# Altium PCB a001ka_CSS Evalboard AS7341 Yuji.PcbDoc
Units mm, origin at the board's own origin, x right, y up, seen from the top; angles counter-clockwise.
Board outline 40 x 29 mm, 4 copper layers (Top Layer, Signal Layer 1, Internal Plane 1, Bottom Layer), stack 1.536 mm thick; 40 components, 22 nets, 130 pads, 47 vias.
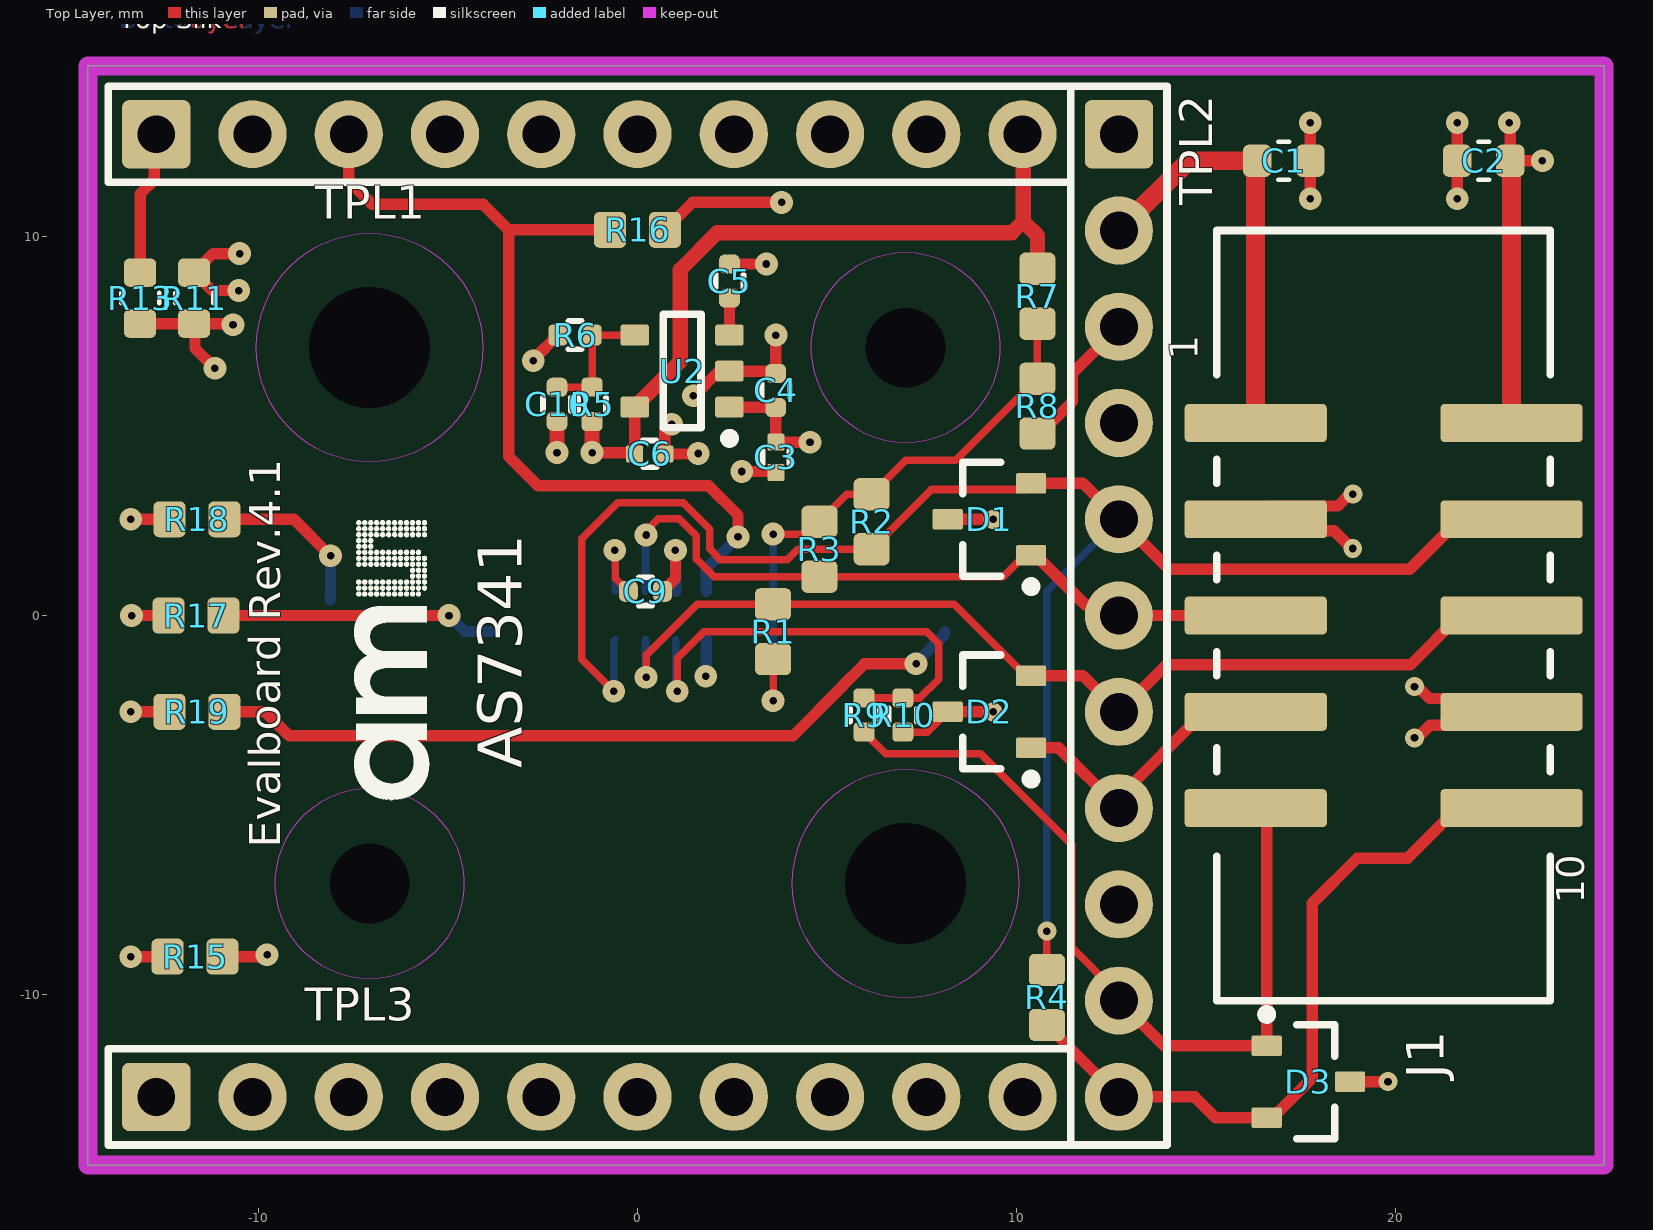
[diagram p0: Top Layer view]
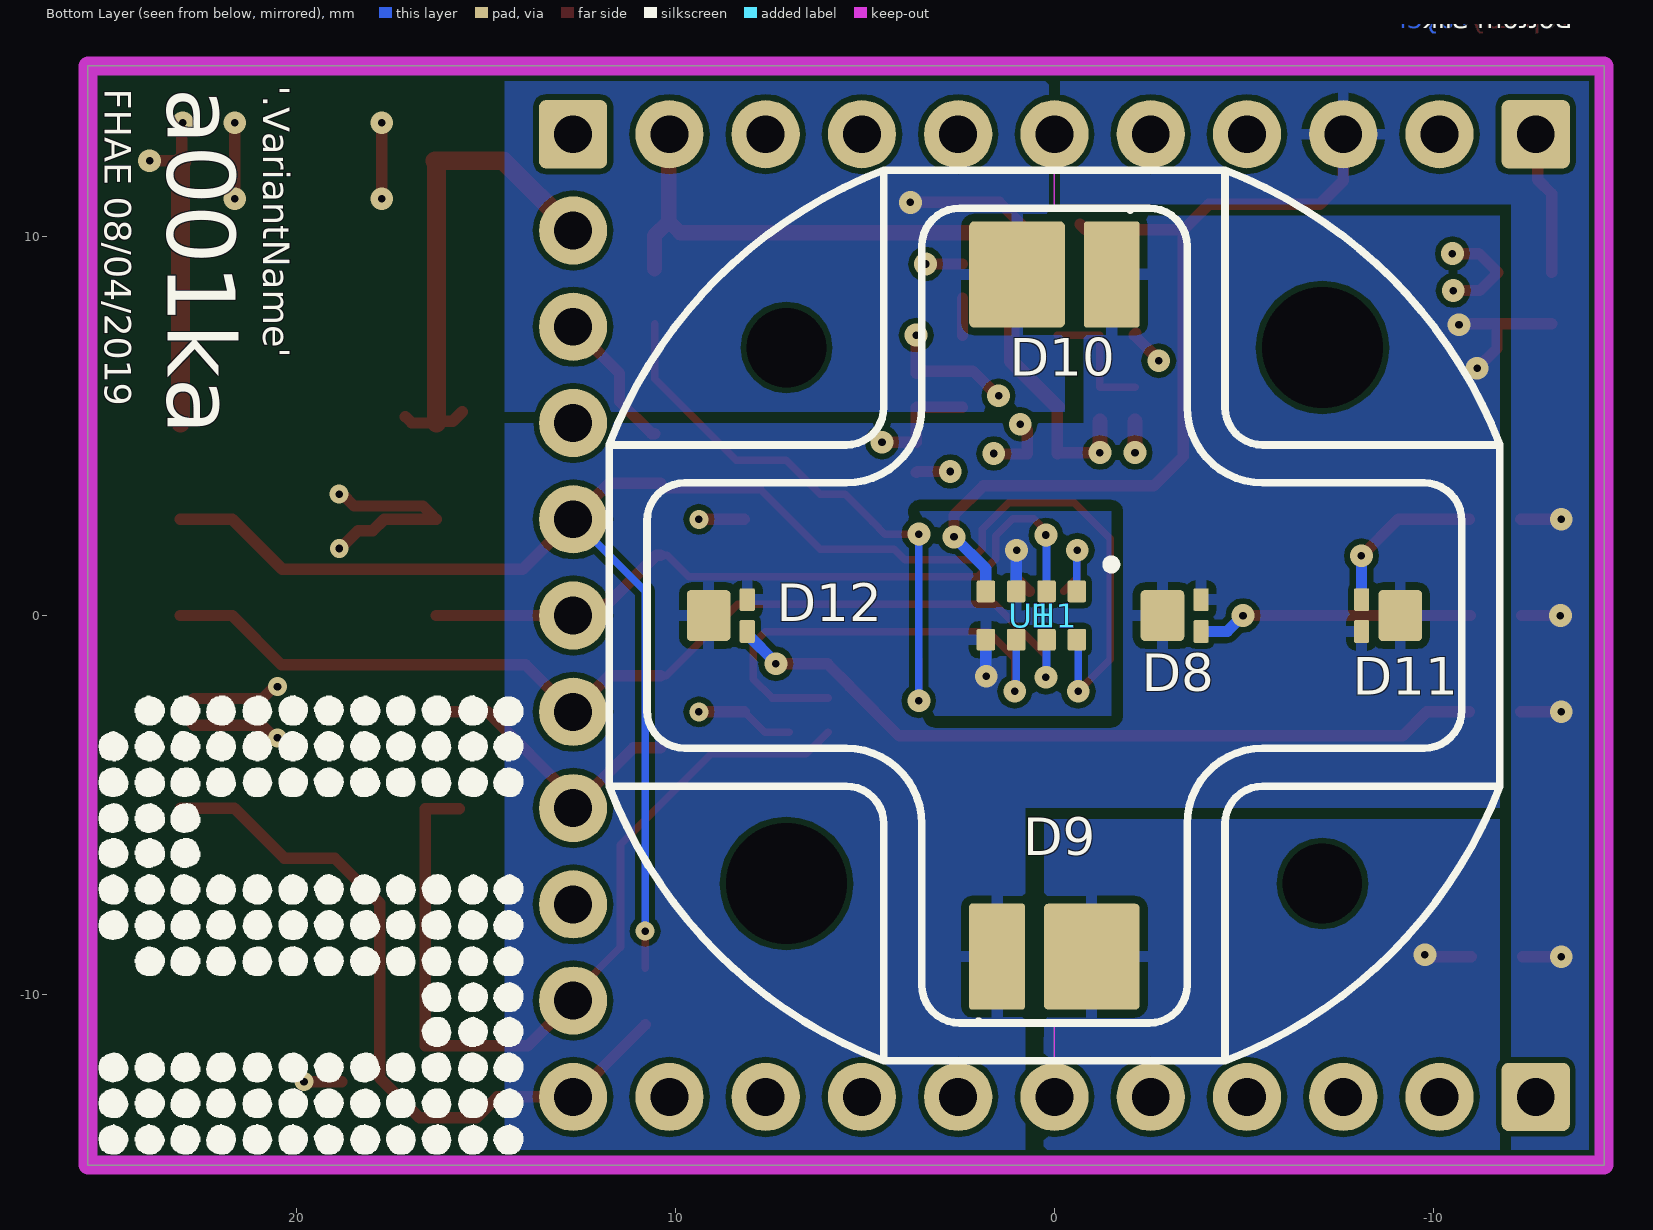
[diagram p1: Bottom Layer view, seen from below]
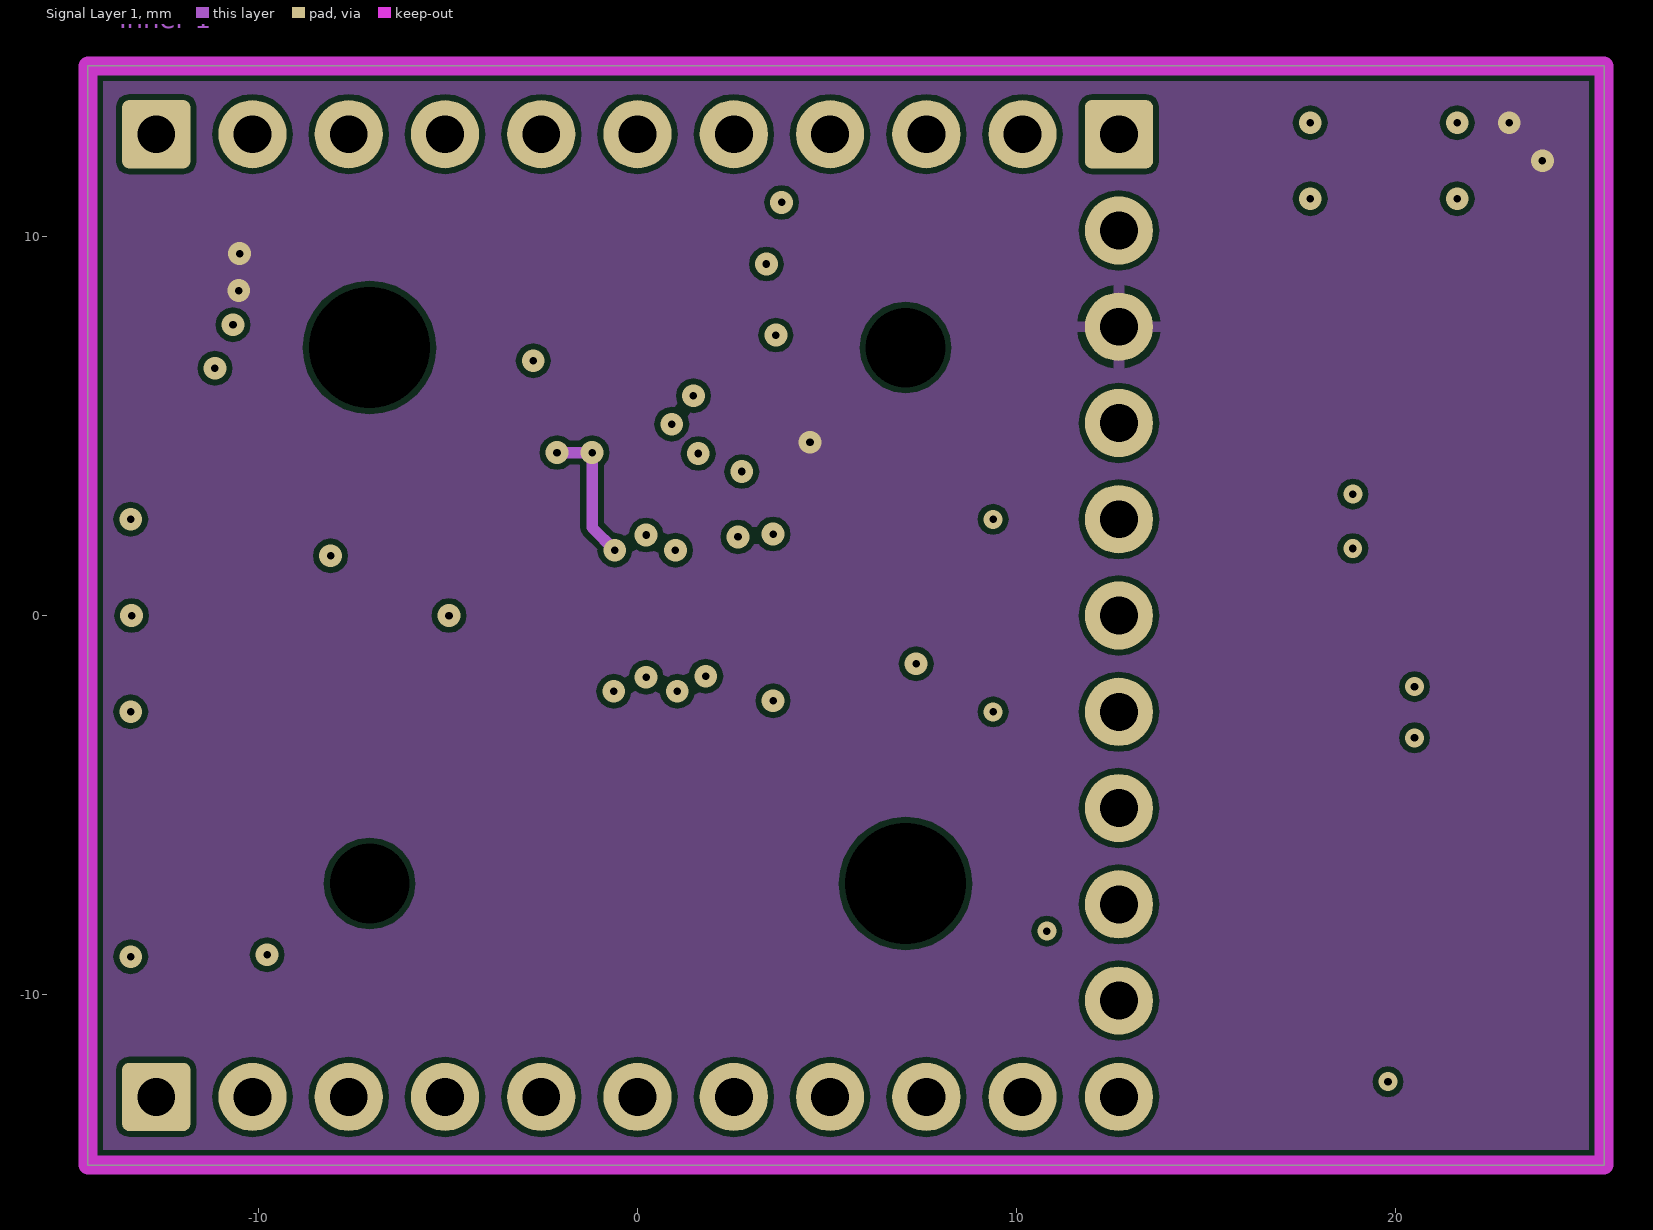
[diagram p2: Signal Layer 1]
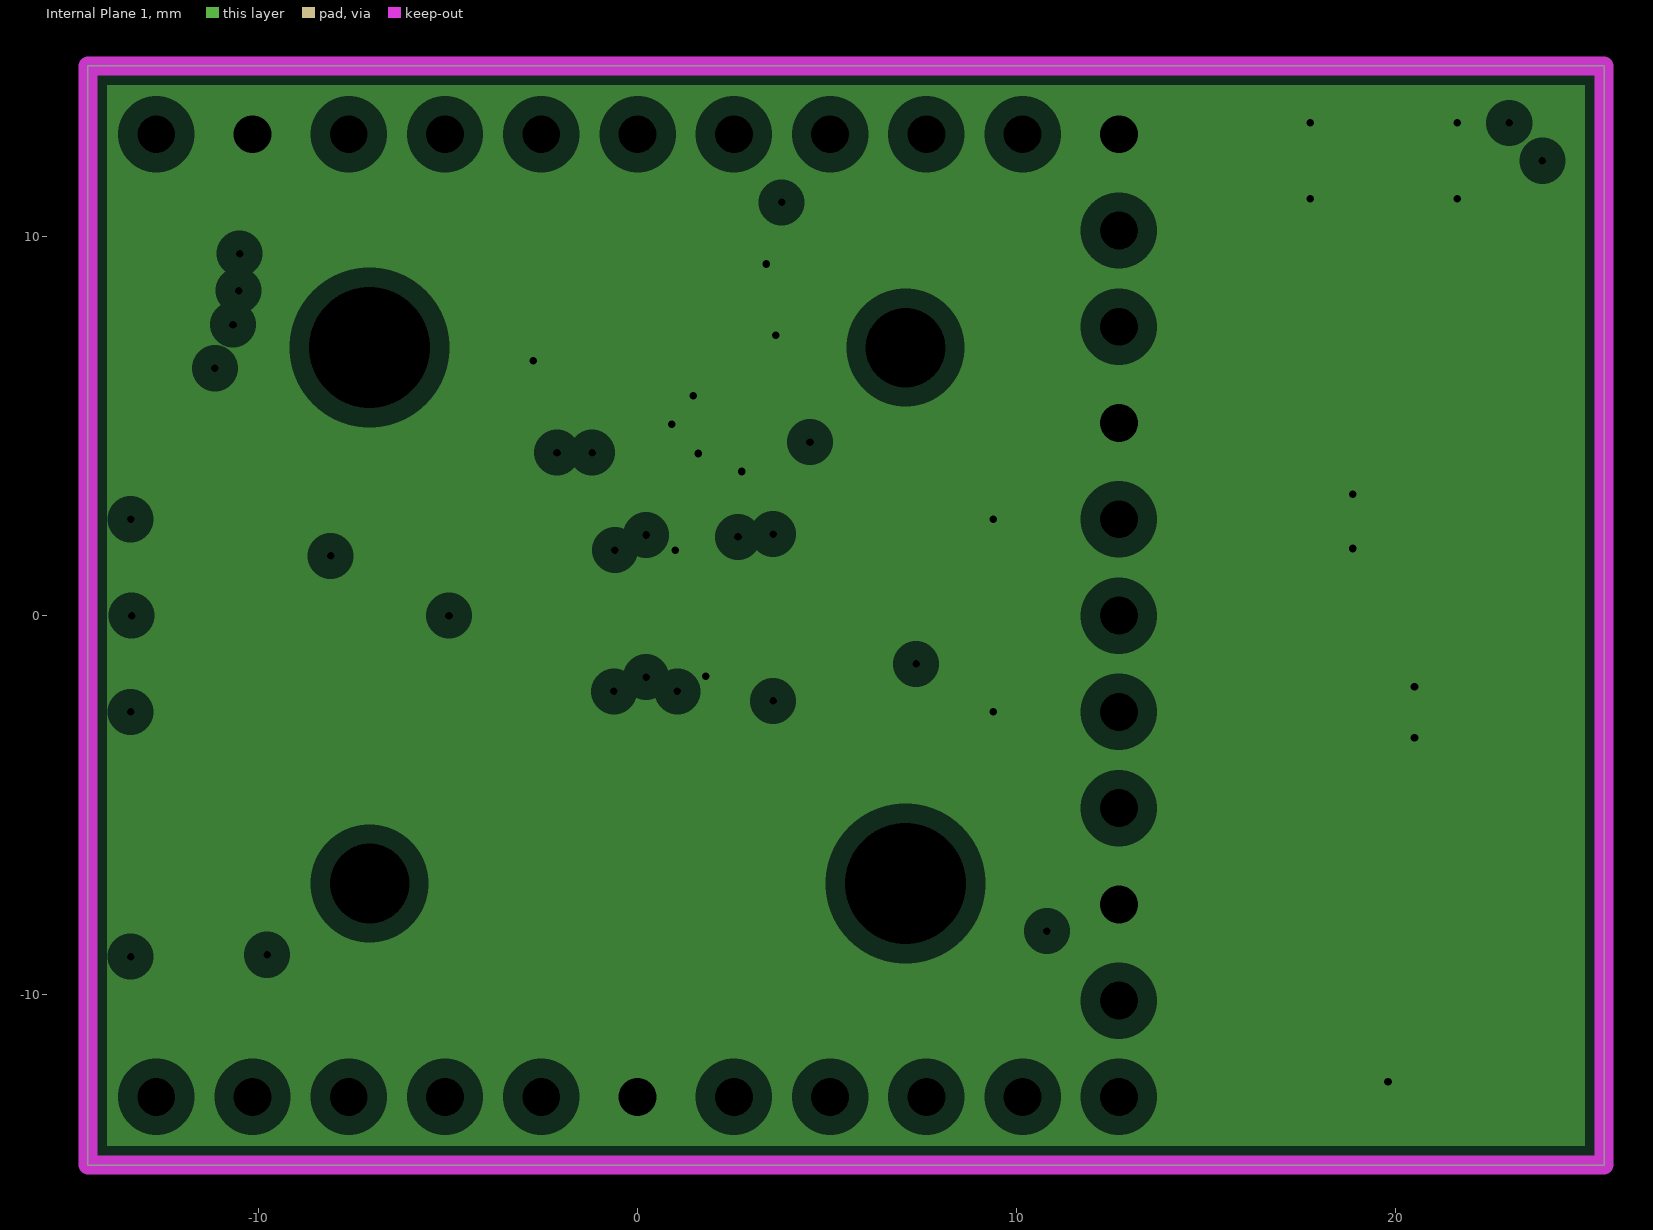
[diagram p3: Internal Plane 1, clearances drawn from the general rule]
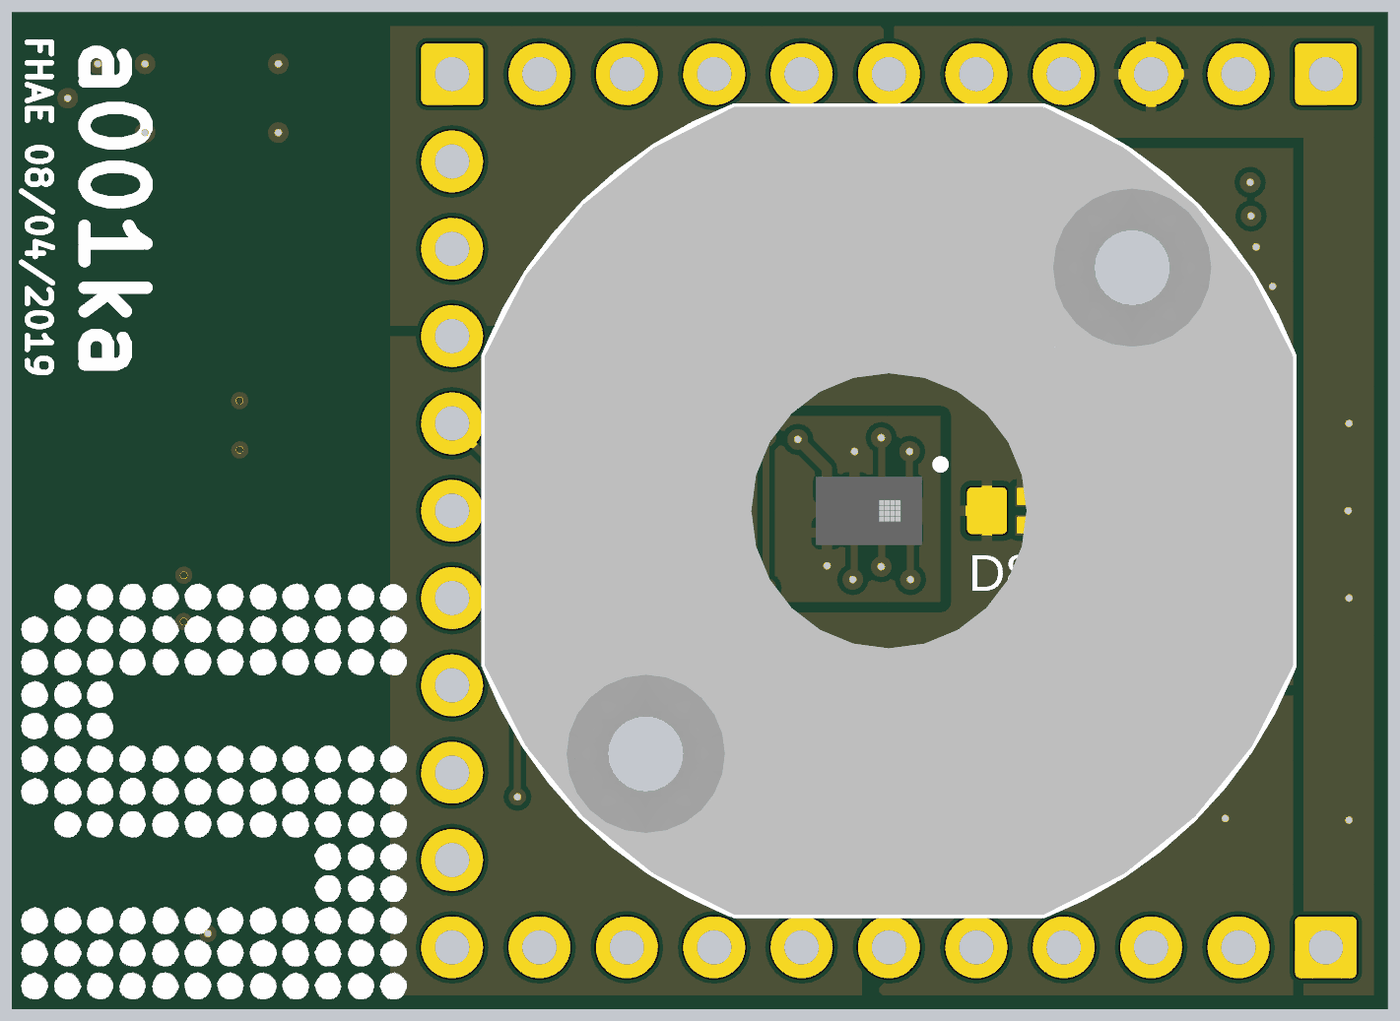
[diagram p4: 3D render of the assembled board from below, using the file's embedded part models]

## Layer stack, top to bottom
Top Solder: solder mask 0.0102, Solder Resist, Dk 3.5
Top Layer: signal copper 0.018
Dielectric 1: core 0.36, FR-4, Dk 4.2
Signal Layer 1: signal copper 0.035
Dielectric 3: prepreg 0.71, Dk 4.2
Internal Plane 1: plane copper 0.035, net GND
Dielectric 2: core 0.36, Dk 4.2
Bottom Layer: signal copper 0.018
Bottom Solder: solder mask 0.0102, Solder Resist, Dk 3.5

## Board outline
-14.5,-14.5 25.5,-14.5 25.5,14.5 -14.5,14.5

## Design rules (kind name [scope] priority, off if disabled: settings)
Clearance [All] p1: gap=0.15 ignorepadtopadclearanceinfootprint=FALSE except(0.3: Fill-Fill Fill-Poly Fill-Region Poly-Poly Poly-Region Region-Region)
ComponentClearance [All] p1: gap=0 collisioncheckmode=3 verticalgap=0 showdistances=FALSE
HoleSize [All] p1: absolutevalues=TRUE maxlimit=5 minlimit=0.025 maxpercent=80.000 minpercent=20.000
MinimumSolderMaskSliver [All] p1: minsoldermaskwidth=0.15
PlaneClearance [All] p1: clearance=0.508
PlaneConnect [All] p1: pad.planeconnectstyle=Relief pad.reliefexpansion=0.508 pad.reliefentries=4 pad.reliefconductorwidth=0.254 pad.reliefairgap=0.254 via.planeconnectstyle=Direct via.reliefexpansion=0.508 via.reliefentries=4 via.reliefconductorwidth=0.254 via.reliefairgap=0.254
PolygonConnect "Via direct connect" [(ObjectKind = 'Via') And (Net = 'LDR') or (ObjectKind = 'Via') And (Net = 'LED_A') or (ObjectKind = 'Via') And (Net = '3V3') or (ObjectKind = 'Via') And (Net = '1V8') or (ObjectKind = 'Via') And (Net = 'I2C_Level')] p1: thpad.connectstyle=Relief thpad.reliefconductorwidth=0.254 thpad.reliefentries=4 thpad.polygonreliefangle="90 Angle" thpad.airgapwidth=0.254 smdpad.connectstyle=Relief smdpad.reliefconductorwidth=0.254 smdpad.reliefentries=4 smdpad.polygonreliefangle="90 Angle" smdpad.airgapwidth=0.254 via.connectstyle=Direct via.reliefconductorwidth=0.254 via.reliefentries=4 via.polygonreliefangle="90 Angle" via.airgapwidth=0.254
PolygonConnect [All] p2: thpad.connectstyle=Relief thpad.reliefconductorwidth=0.3 thpad.reliefentries=4 thpad.polygonreliefangle="90 Angle" thpad.airgapwidth=0.2 smdpad.connectstyle=Relief smdpad.reliefconductorwidth=0.3 smdpad.reliefentries=4 smdpad.polygonreliefangle="90 Angle" smdpad.airgapwidth=0.2 via.connectstyle=Direct via.reliefconductorwidth=0.3 via.reliefentries=4 via.polygonreliefangle="90 Angle" via.airgapwidth=0.2
RoutingVias [All] p1: holewidth=0.2 width=0.6 viastyle="Through Hole" minholewidth=0.15 minwidth=0.55 maxholewidth=2 maxwidth=2
SilkToBoardRegionClearance [All] p1 off:
SilkToSilkClearance [All] p1 off: silktosilkclearance=0.254
SilkToSolderMaskClearance [IsPad] p1 off: minsilkscreentomaskgap=0.254 clearancetoexposedcopper=TRUE
SolderMaskExpansion [All] p1: expansion=0.05
Width [All] p1: maxlimit=2 minlimit=0.15 preferedwidth=0.2
22 further rules are at their usual default settings.

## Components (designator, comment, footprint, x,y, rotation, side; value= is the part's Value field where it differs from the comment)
C1 "10u0" CAPC160x80x90L35L 17.05,12 r180 top
C2 "10u0" CAPC160x80x90L35L 22.325,12 r0 top
C3 "1u00" RESC1005X04L 3.65,4.175 r90 top
C4 "100n" CAPC100X50X55L25L 3.645,5.939 r270 top
C5 "100n" CAPC100X50X55L25L 2.425,8.825 r270 top
C6 "4u70" RESC1005X04L 0.32,4.264 r180 top
C9 "100n" CAPC100X50X55L25L 0.209,0.637 r180 top
C10 "1n00" CAPC100X50X55L25L -2.125,5.575 r90 top
D1 "PESD3V3" SOT23-3L 9.282,2.54 r180 top
D2 "PESD3V3" SOT23-3L 9.282,-2.54 r180 top
D3 "PESD3V3" SOT23-3L 17.7,-12.3 r0 top
D8 "LXZ2-5790-3" "LUXEON Z ES - w/o Paste" -2.95,0 r180 bottom locked
D9 "YJ-VTC-2835-G01-65" YJ-VTC-2835-G01 0,-9 r0 bottom locked
D10 "YJ-VTC-2835-G01-65" YJ-VTC-2835-G01 0,9 r180 bottom locked
D11 "LXZ2-5790-3" "LUXEON Z ES - w/o Paste" -9.025,0 r0 bottom locked
D12 "LXZ2-5790-3" "LUXEON Z ES - w/o Paste" 9.025,0 r180 bottom locked
H1 "Reflective Adptr empty" "a001ga0_Reflective Adptr empty" 0,0 r270 bottom locked
J1 "10 Pin" 61201020621 19.685,0 r270 top locked
R1 "2k20" RESC155X80X55L30N 3.575,-0.425 r270 top
R2 "2k20" RESC155X80X55L30N 6.175,2.475 r270 top
R3 "2k20" RESC155X80X55L30N 4.8,1.75 r270 top
R4 "0R00" RESC155X80X55L30N 10.8,-10.075 r270 top
R5 "15k0" RESC100X50X40L22L -1.2,5.575 r270 top
R6 "33k0" RESC100X50X40L22L -1.65,7.4 r0 top
R7 "0R00" RESC155X80X55L30N 10.55,8.425 r270 top
R8 "0R00" RESC155X80X55L30N 10.55,5.525 r270 top
R9 "8k20" RESC100X50X40L22L 5.975,-2.625 r270 top
R10 "10k0" RESC100X50X40L22L 7,-2.625 r90 top
R11 "0R00" RESC155X80X55L30L -11.7,8.375 r270 top
R13 "0R00" RESC155X80X55L30L -13.125,8.375 r270 top
R15 "10R0" RESC155X80X55L30N -11.675,-9 r0 top
R16 "10R0" RESC155X80X55L30N 0,10.175 r0 top
R17 "10R0" RESC155X80X55L30N -11.65,0 r0 top
R18 "10R0" RESC155X80X55L30N -11.625,2.54 r0 top
R19 "10R0" RESC155X80X55L30N -11.625,-2.54 r0 top
TPL1 "TestPoints" "TP DK 1mm - 10 Pos" -12.7,12.7 r0 top locked
TPL2 "TestPoints" "TP DK 1mm - 11 Pos" 12.7,12.7 r270 top locked
TPL3 "TestPoints" "TP DK 1mm - 10 Pos" -12.7,-12.7 r0 top locked
U1 "AS7341" LGA8C80P2X4_200X310X110 0,0 r270 bottom
U2 "LTC1844ES5-BYP#PBF" SOT95P280X100-5L 1.175,6.45 r180 top

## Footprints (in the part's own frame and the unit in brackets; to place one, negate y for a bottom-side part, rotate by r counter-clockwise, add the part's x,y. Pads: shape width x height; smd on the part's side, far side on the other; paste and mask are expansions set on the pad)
61201020621 [mm] "10 pins, SMT, straight, gold plating"
  rrect20% 1x3.75 smd mask+0.05: 1(-5.08,-3.375) 2(-5.08,3.375) 3(-2.54,-3.375) 4(-2.54,3.375) 5(0,-3.375) 6(0,3.375) 7(2.54,-3.375) 8(2.54,3.375) 9(5.08,-3.375) 10(5.08,3.375)
  silkscreen extent -10.16,-4.4 10.16,4.4, body extent -10.16,-4.75 10.16,4.75, height 10.25
"a001ga0_Reflective Adptr empty" [mm]
  round 0 hole 2.1 unplated mask+0.2: ""(-7.071,-7.071) ""(7.07,7.07)
  round 0 hole 3.2 unplated mask+0.2: ""(-7.071,7.071) ""(7.071,-7.071)
  Top Layer keep-out region: 11.75,0 10.75,0 10.75,-2.5 10.674,-2.883 10.457,-3.207 10.133,-3.424 9.75,-3.5 9.75,-3.5 5.5,-3.5 5.5,-3.5 4.735,-3.652 4.086,-4.086 3.652,-4.735 3.5,-5.5 3.5,-5.5 3.5,-5.5 3.5,-9.75 3.424,-10.133 3.207,-10.457 2.883,-10.674 2.5,-10.75 2.5,-10.75 2.5,-10.75 -2.5,-10.75 -2.5,-10.75 -2.883,-10.674 -3.207,-10.457 -3.424,-10.133 -3.5,-9.75 -3.5,-9.75 -3.5,-5.5 -3.652,-4.735 -4.086,-4.086 -4.735,-3.652 -5.5,-3.5 -5.5,-3.5 -5.5,-3.5 -9.75,-3.5 -10.133,-3.424 -10.457,-3.207 -10.674,-2.883 -10.75,-2.5 -10.75,-2.5 -10.75,0 -11.75,0 -11.75,-4.5 -11.75,-4.5 -8.897,-8.897 -4.5,-11.75 -4.5,-11.75 -4.5,-11.75 4.5,-11.75 4.5,-11.75 8.897,-8.897 11.75,-4.5 11.75,-4.5 11.75,-4.5
  Top Layer keep-out region: -11.75,0 -10.75,0 -10.75,2.5 -10.674,2.883 -10.457,3.207 -10.133,3.424 -9.75,3.5 -9.75,3.5 -5.5,3.5 -5.5,3.5 -4.735,3.652 -4.086,4.086 -3.652,4.735 -3.5,5.5 -3.5,5.5 -3.5,5.5 -3.5,9.75 -3.424,10.133 -3.207,10.457 -2.883,10.674 -2.5,10.75 -2.5,10.75 -2.5,10.75 2.5,10.75 2.5,10.75 2.883,10.674 3.207,10.457 3.424,10.133 3.5,9.75 3.5,9.75 3.5,5.5 3.652,4.735 4.086,4.086 4.735,3.652 5.5,3.5 5.5,3.5 5.5,3.5 9.75,3.5 10.133,3.424 10.457,3.207 10.674,2.883 10.75,2.5 10.75,2.5 10.75,0 11.75,0 11.75,4.5 11.75,4.5 8.897,8.897 4.5,11.75 4.5,11.75 4.5,11.75 -4.5,11.75 -4.5,11.75 -8.897,8.897 -11.75,4.5 -11.75,4.5 -11.75,4.5
  Bottom Layer keep-out region: -9.571,-7.071 -9.324,-5.986 -8.63,-5.116 -7.627,-4.634 -6.515,-4.634 -5.512,-5.116 -4.819,-5.986 -4.571,-7.071 -4.571,-7.071 -4.819,-8.156 -5.512,-9.026 -6.515,-9.508 -7.627,-9.508 -8.63,-9.026 -9.324,-8.156 -9.571,-7.071
  Bottom Layer keep-out region: 4.57,7.07 4.818,8.155 5.511,9.025 6.514,9.507 7.626,9.507 8.629,9.025 9.322,8.155 9.57,7.07 9.57,7.07 9.322,5.985 8.629,5.115 7.626,4.633 6.514,4.633 5.511,5.115 4.818,5.985 4.57,7.07
  Bottom Layer keep-out region: -7.071,4.071 -8.219,4.299 -9.192,4.95 -9.843,5.923 -10.071,7.071 -10.071,7.071 -9.843,8.219 -9.192,9.192 -8.219,9.843 -7.071,10.071 -7.071,10.071 -5.923,9.843 -4.95,9.192 -4.299,8.219 -4.071,7.071 -4.071,7.071 -4.299,5.923 -4.95,4.95 -5.923,4.299 -7.071,4.071
  Bottom Layer keep-out region: 7.071,-10.071 5.923,-9.843 4.95,-9.192 4.299,-8.219 4.071,-7.071 4.071,-7.071 4.299,-5.923 4.95,-4.95 5.923,-4.299 7.071,-4.071 7.071,-4.071 8.219,-4.299 9.192,-4.95 9.843,-5.923 10.071,-7.071 10.071,-7.071 9.843,-8.219 9.192,-9.192 8.219,-9.843 7.071,-10.071
  silkscreen extent -11.75,-11.75 11.75,11.75, body extent -11.75,-11.75 11.75,11.75, height 5.01
CAPC100X50X55L25L [mm] "Capacitor, Chip; 1.00 mm L X 0.50 mm W X 0.55 mm H body"
  rrect60% 0.5x0.55 smd paste+0 mask+0.05: 1(-0.45,0) 2(0.45,0)
  silkscreen extent -0.18,-0.37 0.18,0.37, body extent -0.5,-0.25 0.5,0.25, height 0.55
CAPC160x80x90L35L [mm] "Capacitor, Chip; 1.60 mm L X 0.80 mm W X 0.90 mm H body"
  rrect40% 0.75x0.85 smd paste+0 mask+0.05: 1(-0.7,0) 2(0.7,0)
  silkscreen extent -0.15,-0.5 0.15,0.5, body extent -0.8,-0.4 0.8,0.4, height 0.9
LGA8C80P2X4_200X310X110 [mm] "LGA, 8-Leads, Body 2,00x3,10mmx1,10mm, Pitch 0,80mm"
  rrect20% 0.575x0.488 smd paste-0.03 mask+0.05: 1(-0.637,0.591)
  rrect20% 0.575x0.488 smd mask+0.05: 2(-0.637,-0.209) 3(-0.637,-1.009) 4(-0.637,-1.809) 5(0.637,-1.809) 6(0.637,-1.009) 7(0.637,-0.209) 8(0.637,0.591)
  body extent -1,-2.13 1,0.97, height 1.08
"LUXEON Z ES - w/o Paste" [mm] "LUXEON Z ES is a high power 1.6mm x 2.0mm LED"
  rrect20% 0.4x0.6 smd paste-0.6 mask-0.05: 1(0.92,0.42) 2(0.92,-0.42)
  rrect20% 1.15x1.35 smd paste-0.7 mask+0.05: 3(-0.1,0)
  body extent -0.82,-0.82 1.22,0.82, height 0.68
RESC100X50X40L22L [mm] "Resistor, Chip; 1.00 mm L X 0.50 mm W X 0.40 mm H body"
  rrect40% 0.5x0.55 smd paste+0 mask+0.05: 1(-0.45,0) 2(0.45,0)
  silkscreen extent -0.18,-0.37 0.18,0.37, body extent -0.5,-0.25 0.5,0.25, height 0.4
RESC155X80X55L30L [mm] "Resistor, Chip; 1.55 mm L X 0.80 mm W X 0.55 mm H body"
  rrect40% 0.75x0.85 smd paste+0 mask+0.05: 1(-0.675,0) 2(0.675,0)
  silkscreen extent -0.14,-0.5 0.14,0.5, body extent -0.77,-0.4 0.77,0.4, height 0.55
RESC155X80X55L30N [mm] "Resistor, Chip; 1.55 mm L X 0.80 mm W X 0.55 mm H body"
  rrect35% 0.85x0.95 smd paste+0 mask+0.05: 1(-0.725,0) 2(0.725,0)
  body extent -0.77,-0.4 0.77,0.4, height 0.55
RESC1005X04L [mm] "Chip Resistor, 2-Leads, Body 1,00x0,50mm, IPC High Density"
  rrect20% 0.45x0.45 smd mask+0.05: 1(-0.4,0) 2(0.4,0)
  silkscreen extent -0.18,-0.35 0.18,0.35, body extent -0.53,-0.27 0.53,0.28, height 0.4
SOT23-3L [mm] "SOT23, 3-Leads, Body 2,92x2,37mm, Pitch 0,95mm, IPC High Density"
  rrect20% 0.8x0.55 smd mask+0.05: 1(-1.1,0.95) 2(-1.1,-0.95) 3(1.1,0)
  silkscreen extent -1.23,-1.5 0.7,1.9, body extent -1.13,-1.5 1.13,1.5, height 1.2
SOT95P280X100-5L [mm] "SOT23, 5-Leads, Body 2,90x2,80mm, Pitch 0,95mm, IPC High Density"
  rrect20% 0.75x0.55 smd mask+0.05: 1(-1.25,0.95) 2(-1.25,0) 3(-1.25,-0.95) 4(1.25,-0.95) 5(1.25,0.95)
  silkscreen extent -1.38,-1.5 0.5,1.9, body extent -1.61,-1.5 1.59,1.5, height 0.92
"TP DK 1mm - 10 Pos" [mm] "TP Row"
  rrect20% 1.8x1.8 hole 1: 1(0,0)
  round 1.8 hole 1: 2(2.54,0) 3(5.08,0) 4(7.62,0) 5(10.16,0) 6(12.7,0) 7(15.24,0) 8(17.78,0) 9(20.32,0) 10(22.86,0)
  silkscreen extent -1.27,-1.27 24.13,1.27
"TP DK 1mm - 11 Pos" [mm] "TP Row"
  rrect20% 1.8x1.8 hole 1: 1(0,0)
  round 1.8 hole 1: 2(2.54,0) 3(5.08,0) 4(7.62,0) 5(10.16,0) 6(12.7,0) 7(15.24,0) 8(17.78,0) 9(20.32,0) 10(22.86,0) 11(25.4,0)
  silkscreen extent -1.27,-1.27 26.67,1.27
YJ-VTC-2835-G01 [mm] "YJ-VTC-2835-G01"
  rrect10% 2.53x2.8 smd: 1(-0.985,0)
  rrect10% 1.47x2.8 smd: 2(1.515,0)
  silkscreen extent 1.95,1.65 2.05,1.75, body extent -1.76,-1.4 1.78,1.38, height 0.71

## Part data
C1 C2: library part 10056, "CAP CER 10u0 10% 25V 1608 X5R", Manufacturer 1=Murata, Manufacturer Part Number 1=GRT188R61E106ME13D, Package=1608, Supplier Part Number 1=490-12323-1-ND, Tolerance=10%, Voltage=25V
C3: "1µF ±20% 10V Ceramic Capacitor X5R 0402 (1005 Metric)", Supplier Part Number 1=1276-1448-1-ND
C4 C5 C9: library part 10109, "CAP CER 100n 10% 50V 1005 X7R", Manufacturer 1=Murata, Manufacturer 2=TDK, Manufacturer 3=Taiyo, Manufacturer Part Number 1=GCM155R71H104KE02D, Manufacturer Part Number 2=CGA2B3X7R1H104K050BB, Manufacturer Part Number 3=UMK105B7104KVHF, Package=1005, Supplier Part Number 1=490-10672-1-ND, Tolerance=10%, Voltage=50V
C6: "4.7µF ±20% 10V Ceramic Capacitor X5R 0402 (1005 Metric)", Supplier Part Number 1=1276-1482-1-ND
C10: library part 10097, "CAP CER 1n00 10% 50V 1005 X7R", Manufacturer 1=Murata, Manufacturer 2=TDK, Manufacturer 3=Taiyo, Manufacturer 4=KEMET, Manufacturer Part Number 1=GCM155R71H102KA37D, Manufacturer Part Number 2=CGA2B2X7R1H102K050BA, Manufacturer Part Number 3=UMK105B7102KVHF, Manufacturer Part Number 4=C0402C222K5RACAUTO, Package=1005, Supplier Part Number 1=490-4761-1-ND, Tolerance=10%, Voltage=50V
D1 D2 D3: library part PESD3V3L2BT,215, "26V Clamp 15A (8/20µs) Ipp Tvs Diode Surface Mount TO-236AB", Supplier Part Number 1=509156
D8 D11 D12: "High Power LEDs - White Cool White, 5700K 3-Step, 90 CRI", Supplier Part Number 1=1416-1332-1-ND
D9 D10: "VTC Series High CRI LED SMD - 2835", Manufacturer 1=yujiintl.com
H1: library part "a001ga0_CSS Evalboard Reflective Adptr empty", "a001ga0_CSS Evalboard Reflective Adptr empty"
J1: "10 Positions Header Connector 0.100\" (2.54mm) Surface Mount Gold", Supplier Part Number 1=732-5477-5-ND
R1 R2 R3: library part 20180, "RES SMD 2k20 1% 0.100W 1608 100ppm", Manufacturer 1=Panasonic, Manufacturer 2=Vishay, Manufacturer 3=Stackpole, Manufacturer Part Number 1=ERJ-3EKF2201V, Manufacturer Part Number 2=CRCW06032K20FKEA, Manufacturer Part Number 3=RMCF0603FT2K20, Package=1608, Power=0.100W, Supplier Part Number 1=P2.20KHCT-ND, Tolerance=1%
R4 R7 R8 R11 R13: library part 20123, "RES SMD 0R00 1608", Manufacturer 1=Panasonic, Manufacturer 2=Vishay, Manufacturer 3=Stackpole, Manufacturer 4=Rohm, Manufacturer Part Number 1=ERJ-3GEY0R00V, Manufacturer Part Number 2=CRCW06030000Z0EA, Manufacturer Part Number 3=RMCF0603ZT0R00, Manufacturer Part Number 4=MCR03EZPJ000, Package=1608, Supplier Part Number 1=P0.0GCT-ND
R5: library part 20078, "RES SMD 15k0 1% 0.063W 1005 100ppm", Manufacturer 1=Vishay, Manufacturer Part Number 1=CRCW040215K0FKED, Package=1005, Power=0.063W, Supplier Part Number 1=541-15.0KLCT-ND, Tolerance=1%
R6: library part 20086, "RES SMD 33k0 1% 0.063W 1005 100ppm", Manufacturer 1=Vishay, Manufacturer Part Number 1=CRCW040233K0FKED, Package=1005, Power=0.063W, Supplier Part Number 1=541-33.0KLCT-ND, Tolerance=1%
R9: library part 20072, "RES SMD 8k20 1% 0.063W 1005 100ppm", Manufacturer 1=Vishay, Manufacturer Part Number 1=CRCW04028K20FKED, Package=1005, Power=0.063W, Supplier Part Number 1=541-8.20KLCT-ND, Tolerance=1%
R10: library part 20074, "RES SMD 10k0 1% 0.063W 1005 100ppm", Manufacturer 1=Vishay, Manufacturer 3=Rohm, Manufacturer Part Number 1=CRCW040210K0FKED, Manufacturer Part Number 3=MCR01MZPF1002, Package=1005, Power=0.063W, Supplier Part Number 1=541-10.0KLCT-ND, Tolerance=1%
R15 R16 R17 R18 R19: library part 20124, "RES SMD 10R0 1% 0.100W 1608 100ppm", Manufacturer 1=Panasonic, Manufacturer 2=Vishay, Manufacturer 3=Stackpole, Manufacturer 4=Rohm, Manufacturer Part Number 1=ERJ-3EKF10R0V, Manufacturer Part Number 2=CRCW060310R0FKEA, Manufacturer Part Number 3=RMCF0603FT10R0, Manufacturer Part Number 4=MCR03EZPFX10R0, Package=1608, Power=0.100W, Supplier Part Number 1=P10.0HCT-ND, Tolerance=1%
TPL1 TPL2 TPL3: "1mm, 2,54mm Pitch"
U1: "11-channel spectral sensor frontend", Manufacturer 1=ams, Manufacturer Part Number 1=505670007
U2: "Linear Voltage Regulator IC Positive Adjustable Output 1.25 V ~ 6 V 150mA TSOT-23-5", Manufacturer 1=Linear, Package=TSOT23-5, Supplier Part Number 1=LTC1844ES5-BYP#TRMPBFCT-ND

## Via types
v1: diameter 0.6, hole 0.2, Top Layer to Bottom Layer, tented bottom, 33 vias
v2: diameter 0.5, hole 0.2, Top Layer to Bottom Layer, tented bottom, 8 vias
v3: diameter 0.6, hole 0.2, Top Layer to Bottom Layer, tented both sides, 6 vias

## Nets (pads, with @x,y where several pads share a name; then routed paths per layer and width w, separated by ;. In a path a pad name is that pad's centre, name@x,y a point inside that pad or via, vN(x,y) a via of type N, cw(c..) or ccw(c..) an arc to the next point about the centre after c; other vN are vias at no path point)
1V8: C6.2 C9.2 C10.1 R5.2 R7.1 TPL1.10 U1.1 U2.5 | length 27.5
  Top Layer w0.2: v1(-0.6,1.725) -0.591,1.716 -0.591,0.987 C9.2
  Top Layer w0.3: v1(-1.2,4.3) -0.116,4.3 C6.2 -0.075,4.269 U2.5
  Top Layer w0.4: v1(-2.125,4.3) C10.1 ; v1(-1.2,4.3) R5.2 ; U2.5 1.125,6.7 1.125,9.125 2.1,10.1 9.875,10.1 10.175,10.4 ; TPL1.10 10.175,12.685 10.175,10.4 ; R7.1 10.55,10.025 10.175,10.4
  Signal Layer 1 w0.3: v1(-2.125,4.3) v1(-1.2,4.3) -1.2,2.325 v1(-0.6,1.725)
  Bottom Layer w0.2: v1(-0.6,1.725) -0.591,1.716 U1.1
3V3: C2.2 C3.2 C4.2 J1.2 R8.2 R11.1 TPL2.3 U2.1 | length 18.5
  Top Layer w0.2: J1.2@23.025,5.115 J1.2
  Top Layer w0.3: v1(-10.525,8.575) -10.525,8.625 -10.575,8.575 -11.225,8.575 R11.1 -11.2,9.55 v1(-10.5,9.55) ; U2.1 3.634,5.5 C4.2 3.65,5.484 C3.2 v1(4.55,4.575) ; R8.2 10.625,4.8 11.475,5.65 11.475,6.395 TPL2.3 ; v3(23,13) 23.025,12.975 C2.2 v3(23.875,12)
  Top Layer w0.5: C2.2 23.06,11.965 J1.2
5V0: C1.2 J1.1 TPL2.2 | length 13
  Top Layer w0.3: J1.1@15.625,5.375 15.875,5.125 16.265,5.125 J1.1 16.955,5.08 J1.1@17.125,5.25
  Top Layer w0.5: TPL2.2 14.54,12 C1.2 16.31,11.96 J1.1
GND: C1.1 C2.1 C3.1 C4.1 C5.1 C6.1 C9.1 D1.3 D2.3 D3.3 J1.3 J1.8 R6.1 R10.1 TPL1.2 TPL2.1 TPL2.4 TPL2.9 TPL3.6 U1.3 U1.5 U2.2 | length 31.6
  Top Layer w0.2: R10.1 7.647,-3.075 D2.3
  Top Layer w0.3: v1(-2.75,6.725) -2.75,6.75 R6.1 R6.1@-2.15,7.45 ; C9.1 1,0.978 v1(1,1.725) ; v1(0.9,5.05) 0.875,5.05 0.72,4.895 C6.1 1.589,4.264 v1(1.6,4.275) ; v1(1.475,5.8) 1.475,5.775 2.15,6.45 U2.2 3.584,6.45 C4.1 3.645,7.395 v1(3.65,7.4) ; C5.1 v1(3.4,9.275) ; v1(2.75,3.8) 3.625,3.8 C3.1 ; D2.3 v2(9.381,-2.54) ; D1.3 v2(9.381,2.54) ; J1.3 17.685,2.54 17.99,2.235 18.375,2.235 18.783,1.827 18.813,1.827 v2(18.87,1.77) ; J1.3@16.41,2.64 16.66,2.89 18.48,2.89 18.794,3.204 v2(18.875,3.204) ; v3(17.75,11) C1.1 v3(17.75,13) ; D3.3 v2(19.8,-12.3) ; v2(20.5,-3.225) 20.581,-3.225 20.916,-2.89 22.71,-2.89 J1.8 22.71,-2.19 20.896,-2.19 20.581,-1.875 v2(20.5,-1.875) ; v3(21.625,11) C2.1 v3(21.625,13)
  Bottom Layer w0.3: v1(1,1.725) 1,1.75 1.009,1.741 U1.3 ; v1(1.8,-1.6) 1.809,-1.591 U1.5
GPIO: R9.1 R10.2 U1.6 | length 12.7
  Top Layer w0.2: v1(1.05,-2) 1.05,-1.125 1.75,-0.425 7.625,-0.425 7.95,-0.75 7.95,-1.675 7.45,-2.175 R10.2 R9.1
  Bottom Layer w0.2: U1.6 1.009,-1.959 v1(1.05,-2)
GPIO2: D2.1 J1.7 TPL2.8 | length 7.8
  Top Layer w0.3: D2.1 11.11,-3.49 TPL2.8 12.7,-4.8 14.96,-2.54 J1.7
GPIO3: D3.1 J1.9 R9.2 TPL2.10 | length 22.9
  Top Layer w0.2: R9.2 6.55,-3.65 9.05,-3.65 11.45,-6.05 11.45,-8.75 12.7,-10 TPL2.10
  Top Layer w0.3: TPL2.10 13.89,-11.35 D3.1 16.6,-5.1 J1.9@15.7,-5.1
I2C_Level: R1.2 R2.1 R3.1 R7.2 R8.1 | length 15.6
  Top Layer w0.2: v1(3.575,-2.25) R1.2 ; v1(3.575,2.15) 4.475,2.15 R3.1 5.525,3.2 R2.1 7.075,4.1 8.4,4.1 R8.1 R7.2
  Bottom Layer w0.2: v1(3.575,-2.25) v1(3.575,2.15)
INT: D2.2 J1.6 R1.1 TPL2.7 U1.7 | length 27.6
  Top Layer w0.2: v1(0.225,-1.625) 0.225,-1.05 1.575,0.3 R1.1 8.35,0.3 10.24,-1.59 D2.2 D2.2@10.391,-1.59
  Top Layer w0.3: D2.2@10.391,-1.59 11.75,-1.59 TPL2.7 12.709,-2.54 13.948,-1.301 20.393,-1.301 21.694,0 J1.6 J1.6@23.069,0
  Bottom Layer w0.2: U1.7 0.209,-1.784 0.225,-1.8 v1(0.225,-1.625)
LDR: R15.1 R16.1 R17.1 R18.1 R19.1 TPL1.3 U1.4 | length 28
  Top Layer w0.3: v1(-13.375,-9) R15.1 R15.1@-12.35,-9 ; v1(-13.375,-2.54) R19.1 R19.1@-12.3,-2.54 ; v1(-13.375,2.54) R18.1 R18.1@-12.3,2.54 ; v1(-13.35,0) R17.1 R17.1@-12.325,0 ; TPL1.3 -7.62,11.47 -7,10.85 -4.075,10.85 -3.4,10.175 ; R16.1@-0.675,10.325 -0.825,10.175 -3.4,10.175 ; v1(2.65,2.075) 2.65,2.65 1.875,3.425 -2.625,3.425 -3.4,4.2 -3.4,10.175
  Bottom Layer w0.3: U1.4 1.809,1.234 v1(2.65,2.075)
LDR_D8: D8.2 R17.2 | length 7.3
  Top Layer w0.3: R17.2@-10.975,0 R17.2 v1(-4.975,0)
  Bottom Layer w0.3: v1(-4.975,0) -4.555,-0.42 D8.2
LDR_D9: D9.1 R15.2 | length 1.2
  Top Layer w0.3: R15.2@-11,-9 R15.2 -9.925,-9 -9.875,-8.95 v1(-9.775,-8.95)
LDR_D10: D10.1 R16.2 | length 3.4
  Top Layer w0.3: R16.2@0.675,10.175 R16.2 1.45,10.9 v1(3.8,10.9)
LDR_D11: D11.2 R18.2 | length 4.4
  Top Layer w0.3: R18.2@-10.95,2.54 R18.2 -9.065,2.54 v1(-8.1,1.575)
  Bottom Layer w0.3: D11.2 -8.1,0.425 v1(-8.1,1.575)
LDR_D12: D12.2 R19.2 | length 20.5
  Top Layer w0.3: R19.2@-10.95,-2.54 R19.2 -9.825,-2.54 -9.19,-3.175 4.1,-3.175 5.4,-1.875 5.4,-1.859 5.984,-1.275 v1(7.35,-1.275)
  Bottom Layer w0.3: v1(7.35,-1.275) 7.35,-1.25 8.105,-0.495 D12.2
LED_A: D8.1 D8.3 D9.2 D10.2 D11.1 D11.3 D12.1 D12.3 R11.2 R13.2 | length 3.9
  Top Layer w0.3: R13.2 R11.2 R11.2@-11.674,7.7 ; v1(-11.15,6.525) -11.675,7.05 -11.675,7.699 R11.2@-11.674,7.7 ; v1(-10.675,7.675) -10.7,7.7 R11.2@-11.674,7.7
NetC5_2: C5.2 U2.3 | length 1
  Top Layer w0.3: U2.3 C5.2
NetC10_2: C10.2 R5.1 R6.2 U2.4 | length 3.4
  Top Layer w0.2: C10.2 R5.1 R6.2 U2.4
SCL: D1.1 J1.5 R3.2 TPL2.6 U1.2 | length 19.7
  Top Layer w0.2: v1(0.225,2.125) 0.225,2.175 0.2,2.2 0.55,2.55 1.1,2.55 1.55,2.1 1.55,1.493 2.018,1.025 R3.2 9.65,1.025 10.215,1.59 D1.1
  Top Layer w0.3: D1.1 10.507,1.59 11.81,0.287 12.413,0.287 TPL2.6 J1.5
  Bottom Layer w0.2: U1.2 0.209,2.109 v1(0.225,2.125)
SDA: D1.2 J1.4 R2.2 R4.1 TPL2.5 U1.8 | length 46.6
  Top Layer w0.2: v1(-0.625,-2) -1.475,-1.15 -1.475,2.025 -0.525,2.975 1.2,2.975 1.9,2.275 1.9,1.759 2.184,1.475 3.95,1.475 4.225,1.75 R2.2 7.75,3.325 10.217,3.325 D1.2 ; R4.1@10.8,-9.3 v2(10.8,-8.325)
  Top Layer w0.3: D1.2@10.391,3.49 11.75,3.49 TPL2.5 12.709,2.54 14.029,1.22 20.374,1.22 21.694,2.54 J1.4@23.069,2.54
  Bottom Layer w0.2: v1(-0.625,-2) -0.625,-0.672 U1.8 ; v2(10.8,-8.325) 10.8,0.64 TPL2.5
SDA2: D3.2 J1.10 R4.2 TPL2.11 | length 19.4
  Top Layer w0.3: R4.2 TPL2.11 14.7,-12.7 15.25,-13.25 D3.2 16.75,-13.25 17.8,-12.2 17.8,-7.592 18.992,-6.4 20.323,-6.4 21.643,-5.08 J1.10
Vext: R13.1 TPL1.1 | length 3.8
  Top Layer w0.3: R13.1 -13.125,11.125 -12.75,11.5 -12.75,12.65 TPL1.1
pads on no net: H1. TPL1.4 TPL1.5 TPL1.6 TPL1.7 TPL1.8 TPL1.9 TPL3.1 TPL3.2 TPL3.3 TPL3.4 TPL3.5 TPL3.7 TPL3.8 TPL3.9 TPL3.10

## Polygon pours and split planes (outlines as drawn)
LDR_D9 on Bottom Layer "LDR_D9" (solid, pour order 23): -11.75,-5.375 0.272,-5.375 0.277,-14.5 -11.75,-14.5
LDR_D10 on Bottom Layer "LDR_D10" (solid, pour order 21): -0.275,5.375 -0.275,14.1 14.5,14.1 14.5,5.38
LED_A on Bottom Layer "LED Anode" (solid, remove dead copper, pour order 13): 14.5,5.075 14.5,-14.5 0.775,-14.5 0.775,-5.075 -11.75,-5.075 -11.75,10.55 -0.775,10.55 -0.775,5.075
LDR on Bottom Layer "LED LDR" (solid, pour order 2): -0.15,14.5 -14.5,14.5 -14.5,-14.5 -12.05,-14.5 -12.05,10.85 -0.15,10.85
GND on Bottom Layer "Sensor GND Shield" (solid, pour order 0): -1.5,2.75 -1.5,-2.65 3.625,-2.65 3.625,2.75
3V3 on Signal Layer 1 "3V3" (solid, pour order 19): 5.15,-14.5 25.5,-14.5 25.5,14.5 -14.5,14.5 -14.5,5.15 -14.5,-14.5
GND on Internal Plane 1 (split plane): 24.99,-13.99 -13.99,-13.99 -13.99,13.99 24.99,13.99

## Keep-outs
Keep-Out Layer:
  the board outline again, w0.5

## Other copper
Top Layer:
  text "Top Layer" at -13.675,15.5 h0.5
Signal Layer 1:
  text "Inner 1" at -13.675,15.5 h0.5
Bottom Layer:
  text "Bottom Layer" at -13.675,15.5 h0.5
Internal Plane 1 (plane layer: these items are gaps in the copper):
  text "Inner 2" at -13.675,15.5 h0.5

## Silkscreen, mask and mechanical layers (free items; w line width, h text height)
Top Overlay:
  drawing of 120 lines, arcs and shapes, not listed
  text "Top Silk" at -13.675,15.5 h0.5
  text "AS7341" at -2.675,-4.025 h2 r90
  text "Evalboard Rev.4.1" at -9.15,-6.125 h1.4 r90
Bottom Overlay:
  drawing of 119 lines, arcs and shapes, not listed
  text "Bottom Silk" at -13.675,15.5 h0.5
  text "'.VariantName'" at 20.875,13.975 h0.7 r90
  text "a001ka" at 23.4,13.925 h1.8 r90
  text "FHAE 08/04/2019" at 25.055,13.9 h0.7 r90
Top Paste:
  text "Top Paste" at -13.675,15.5 h0.5
Bottom Paste:
  text "Bottom Paste" at -13.675,15.5 h0.5
Top Solder:
  text "Top Solder" at -13.675,15.5 h0.5
Bottom Solder:
  text "Bottom Solder" at -13.675,15.5 h0.5
Mechanical 1:
  the board outline again, w0.2
  text "Board Outline" at -13.675,15.5 h0.5
Drawings:
  drawing of 153 lines, arcs and shapes, not listed
Panel:
  lines w0.1: -14.5,14.5 -14.5,43.5 ; -14.5,14.5 14.5,14.5 ; -14.5,14.5 14.5,14.5 ; -14.5,14.5 -14.5,-14.5 14.5,-14.5 ; -14.5,43.5 -14.5,72.5 ; -14.5,43.5 14.5,43.5 ; -14.5,43.5 14.5,43.5 ; -14.5,43.5 14.5,43.5 ; -14.5,72.5 -14.5,101.5 14.5,101.5 ; -14.5,72.5 14.5,72.5 ; -14.5,72.5 14.5,72.5 ; -14.5,72.5 14.5,72.5 ; 14.5,-14.5 ccw(c16.25,-14.504) 18,-14.5 ; 14.5,-14.5 14.5,14.5 ; 14.5,14.5 14.5,43.5 ; 14.5,43.5 14.5,72.5 ; 14.5,72.5 14.5,101.5 ; 14.5,101.5 cw(c16.25,101.504) 18,101.5 ; 18,-14.5 18,14.5 ; 18,-14.5 47,-14.5 ; 18,14.5 18,43.5 ; 18,14.5 47,14.5 ; 18,14.5 47,14.5 ; 18,43.5 18,72.5 ; 18,43.5 47,43.5 ; 18,43.5 47,43.5 ; 18,43.5 47,43.5 ; 18,72.5 18,101.5 ; 18,72.5 47,72.5 ; 18,72.5 47,72.5 ; 18,72.5 47,72.5 ; 18,101.5 47,101.5 ; 47,-14.5 ccw(c48.75,-14.504) 50.5,-14.5 ; 47,-14.5 47,14.5 ; 47,14.5 47,43.5 ; 47,43.5 47,72.5 ; 47,72.5 47,101.5 ; 47,101.5 cw(c48.75,101.504) 50.5,101.5 ; 50.5,-14.5 50.5,14.5 ; 50.5,-14.5 79.5,-14.5 ; 50.5,14.5 50.5,43.5 ; 50.5,14.5 79.5,14.5 ; 50.5,14.5 79.5,14.5 ; 50.5,43.5 50.5,72.5 ; 50.5,43.5 79.5,43.5 ; 50.5,43.5 79.5,43.5 ; 50.5,43.5 79.5,43.5 ; 50.5,72.5 79.5,72.5 ; 50.5,72.5 50.5,101.5 ; 50.5,72.5 79.5,72.5 ; 50.5,72.5 79.5,72.5 ; 50.5,101.5 79.5,101.5 ; 79.5,-14.5 ccw(c81.25,-14.504) 83,-14.5 ; 79.5,-14.5 79.5,14.5 ; 79.5,14.5 79.5,43.5 ; 79.5,43.5 79.5,72.5 ; 79.5,72.5 79.5,101.5 ; 79.5,101.5 cw(c81.25,101.504) 83,101.5 ; 83,-14.5 83,14.5 ; 83,-14.5 112,-14.5 ; 83,14.5 83,43.5 ; 83,14.5 112,14.5 ; 83,14.5 112,14.5 ; 83,43.5 83,72.5 ; 83,43.5 112,43.5 ; 83,43.5 112,43.5 ; 83,43.5 112,43.5 ; 83,72.5 83,101.5 ; 83,72.5 112,72.5 ; 83,72.5 112,72.5 ; 83,72.5 112,72.5 ; 83,101.5 112,101.5 ; 112,-14.5 ccw(c113.75,-14.504) 115.5,-14.5 ; 112,-14.5 112,14.5 ; 112,14.5 112,43.5 ; 112,43.5 112,72.5 ; 112,72.5 112,101.5 ; 112,101.5 cw(c113.75,101.504) 115.5,101.5 ; 115.5,-14.5 115.5,14.5 ; 115.5,-14.5 144.5,-14.5 ; 115.5,14.5 115.5,43.5 ; 115.5,14.5 144.5,14.5 ; 115.5,14.5 144.5,14.5 ; 115.5,43.5 115.5,72.5 ; 115.5,43.5 144.5,43.5 ; 115.5,43.5 144.5,43.5 ; 115.5,43.5 144.5,43.5 ; 115.5,72.5 115.5,101.5 ; 115.5,72.5 144.5,72.5 ; 115.5,72.5 144.5,72.5 ; 115.5,72.5 144.5,72.5 ; 115.5,101.5 144.5,101.5 ; 144.5,-14.5 ccw(c146.25,-14.504) 148,-14.5 148,101.5 ccw(c146.25,101.504) 144.5,101.5 ; 144.5,-14.5 144.5,14.5 ; 144.5,14.5 144.5,43.5 ; 144.5,43.5 144.5,72.5 ; 144.5,72.5 144.5,101.5
  lines w0.3: -24.5,-24.5 -24.5,111.5 158,111.5 158,-24.5 -24.5,-24.5
  lines w0.4: -29.5,-14.5 163,-14.5 ; -29.5,14.5 163,14.5 ; -29.5,43.5 163,43.5 ; -29.5,72.5 163,72.5 ; -29.5,101.5 163,101.5
  text "V-cut" at -37.875,101 h1.52
  text "V-cut" at -37.875,72 h1.52
  text "V-cut" at -37.875,43 h1.52
  text "V-cut" at -37.875,14 h1.52
  text "V-cut" at -37.875,-15 h1.52
Custom Silk Top:
  lines w0.2: 8.375,9.625 8.375,12.375
  text "RGOE | RGOE" at -10.5,11.872 h0.5
  text "13/11/2017" at -10.5,11.372 h0.5
  text "TPL2" at 9.625,9.625 h1.52 r90
  text "3V3" at 6.375,9.375 h1 r90
  text "Vext" at -4.125,9.125 h1 r90
  text "GND" at -2.625,9 h1 r90
  text "GND" at 7.75,9 h1 r90
  text "1" at 11.5,8.75 h2 r90
  text "SDA S" at -1.125,8.375 h1 r90
  text "TX/SDA S" at 0.375,7 h1 r90
  text "RX/SCL S" at 1.875,7 h1 r90
  text "TP3" at -3.875,6.875 h1
  text "JP1" at 4.35,6.875 h1.52 r90
  text "INT/SCL S" at 3.375,6.75 h1 r90
  text "ADDR/INT" at 4.875,6.625 h1 r90
  text "TP4" at -3.875,5.75 h1
  text "1" at 10.85,5.45 h1.7 r90
  text "open" at 6.375,3 h1.52 r90
  text "close" at 7.75,2.75 h1.52 r90
  text "J2" at -8.25,2 h1.52 r90
  text "close" at 6.375,-0.375 h1.52 r90
  text "open" at 7.75,-0.375 h1.52 r90
  text "I²C" at 7.75,-2.375 h1.52 r90
  text "JP2" at 4.75,-3 h1.52 r90
  text "UART" at 6.375,-4 h1.52 r90
  text "J1" at 10.625,-5.563 h1.52 r90
  text "I2C EN" at -5.625,-10.75 h1 r90
  text "CSN SD" at -4.125,-10.75 h1 r90
  text "LED IND" at -2.625,-10.75 h1 r90
  text "RESN" at -1.125,-10.75 h1 r90
  text "SCL M" at 0.375,-10.75 h1 r90
  text "LED DRV" at 1.875,-10.75 h1 r90
  text "SDA M" at 3.375,-10.75 h1 r90
  text "Pin19" at 4.505,-10.76 h1 r90

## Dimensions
-29.5,-14.5 to -29.5,14.5 on Mechanical 16
-14.5,-14.5 to -24.5,-24.5 on Mechanical 16
14.5,101.5 to 18,101.5 on Mechanical 16
-14.5,101.5 to -24.5,111.5 on Mechanical 16
-14.5,101.5 to 14.5,72.5 on Mechanical 16
158,-24.5 to 158,111.5 on Mechanical 16
-24.5,-24.5 to 158,-24.5 on Mechanical 16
